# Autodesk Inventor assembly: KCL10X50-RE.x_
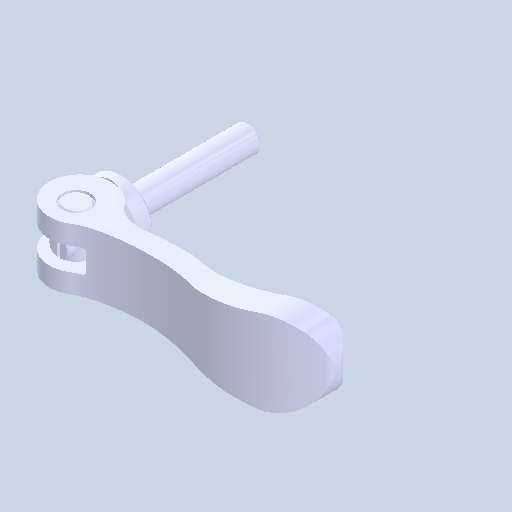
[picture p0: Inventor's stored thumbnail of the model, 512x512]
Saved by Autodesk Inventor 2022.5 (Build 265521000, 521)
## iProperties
Created: 2024-08
Part Number: KCL10X50-RE.x_
Document SubType Name: Assembly
Designer: ImaoCorp
Author: ImaoCorp
Sending System: SOLIDWORKS 2022-2022290
MC: AMD64
MC_MODEL: Intel64 Family 6 Model 60 Stepping 3, GenuineIntel
OS: Windows_NT
FRU: Parasolid Version 33.1, build 260,  4-25-2022
FORMAT: text
GUISE: transmit
KEY: FILEKCL10X50-RE.x_t
DATE: Thu Aug 29 10:51:15 2024
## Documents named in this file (5)
- Y:\5.更新分\2024年対応\1001_KCL\データ\kcl10x50-re\KCL10X50-RE.x_.iam
- Y:\5.更新分\2024年対応\1001_KCL\データ\kcl10x50-re\KCL10X50-RE_01.ipt
- Y:\5.更新分\2024年対応\1001_KCL\データ\kcl10x50-re\KCL10X50-RE_02.ipt
- Y:\5.更新分\2024年対応\1001_KCL\データ\kcl10x50-re\KCL10X50-RE_03.ipt
- Y:\5.更新分\2024年対応\1001_KCL\データ\kcl10x50-re\KCL10X50-RE_04.ipt
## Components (4 placed, 4 different names)
1. KCL10X50-RE_01
2. KCL10X50-RE_02
3. KCL10X50-RE_03
4. KCL10X50-RE_04
